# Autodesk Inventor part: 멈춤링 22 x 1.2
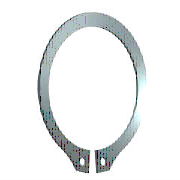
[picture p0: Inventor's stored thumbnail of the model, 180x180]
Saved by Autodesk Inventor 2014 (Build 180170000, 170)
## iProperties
IsCustomPart: 0
Company: 한국ATC센터
Created: 2009-02
Part Number: 멈춤링 22 x 1.2
Material: Steel, Mild
Description: 리테이닝 링(C형)
Document SubType Name: Modeling
Standard: KS B 1336
Designer: KYOUNG IL JANG
Standards Organization: KS
Language: ko-KR
Size Designation: 22 x 1.2
Categories: <MemberInstance><Categories><Category DisplayName="샤프트 부품" InternalName="7f7aeb1f-a693-4053-b835-cee3144e0d98" Mnemonic="SHFT"><Category DisplayName="써클립" Inter
Density: 7.86 g/cm^3
Mass: 1.82859 g
Surface Area: 5.91219 cm^2
Volume: 0.232645 cm^3
Appearance: Metal-Steel
Author: KYOUNG IL JANG
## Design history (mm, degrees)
sketch "스케치1"
  geometry: L1 (-6, 0)-(6, 0) reference; L2 (0, 20.189)-(0, -80.536) reference; L3 (-48.09, 0)-(48.09, 0) reference; L4 (-0.5, -21.488)-(-0.5, -25.588); L5 (-0.5, -6.54)-(-0.5, -13.29); L6 (-2.795, 2.7)-(3.672, 2.7); L7 (0.5, -6.54)-(0.5, -13.29); L8 (0.5, -21.488)-(0.5, -25.588); C1 r 1 at (-2, -23.437); C2 r 1 at (2, -23.437); A1 r 10.5 centre (0, -11) between (0.5, -21.488) and (-0.5, -21.488); A2 r 13.025 centre (0, -10.325) between (5.149, -22.289) and (-5.149, -22.289); A3 r 14.597 centre (0, -11) between (-2.318, -25.411) and (-0.5, -25.588); A4 r 2 centre (-2, -23.437) between (-3.97, -23.781) and (-2.318, -25.411); A5 r 2 centre (-5.94, -24.126) between (-3.97, -23.781) and (-5.149, -22.289); A6 r 2 centre (5.94, -24.126) between (5.149, -22.289) and (3.97, -23.781); A7 r 2 centre (2, -23.437) between (2.318, -25.411) and (3.97, -23.781); A8 r 14.597 centre (0, -11) between (0.5, -25.588) and (2.318, -25.411)
  constraints: 16 point on circle, 12 end point, 10 centre point, 9 symmetric about line, 5 point on line, 4 tangent, 3 coincident, 2 horizontal, 1 perpendicular, 1 vertical, 5 other
  dimensions: "d0" = 21 diameter of A1 (= ND); "d1" = 4.1 distance of L4.end L4.start (= SRB2); "d6" = 0.5 distance between parallel lines of L2 L5 (= 0.25 x SD5); "d7" = 2.7 distance between parallel lines of L6 L3 (= SRB1); "d8" = 0.675 distance of A1.centre A2.centre (= 0.25 x SRB1); "d9" = 2 radius of A4 (= SD5); "d10" = 2 radius of A5 (= SD5); "d11" = 1.5 distance from line of L4 A4.centre (= 0.75 x SD5); "d12" = 2 diameter of C1 (= SD5); "d13" = 2 diameter of C2 (= SD5); "d14" = 11 distance from line of A1.centre L1 (= 0.5 x WD)
extrude "본체" new body sketch "스케치1" distance "d2" = 1.2 (= SD); taper "d3" = 0 deg
workaxis "Work Axis1"
workplane "Work Plane1"
body "Solid1"
other parameters: "WD" = 22 (= WDMIN) [user parameter; used in 1 equation term], "SD" = 1.2 [user parameter; used in 1 equation term], "SRB1" = 2.7 [user parameter; used in 2 equation terms], "ND" = 21 [user parameter; used in 1 equation term], "SRB2" = 4.1 [user parameter; used in 1 equation term], "SD5" = 2 [user parameter; used in 6 equation terms], "d15" = 0, "d16" = 0, "d17" = 0, "d41" = 0, "d42" = 0, "WDMIN" = 22 [user parameter; used in 1 equation term], "SD3" = 20.5 [user parameter], "WDMAX" = 24 [user parameter]
